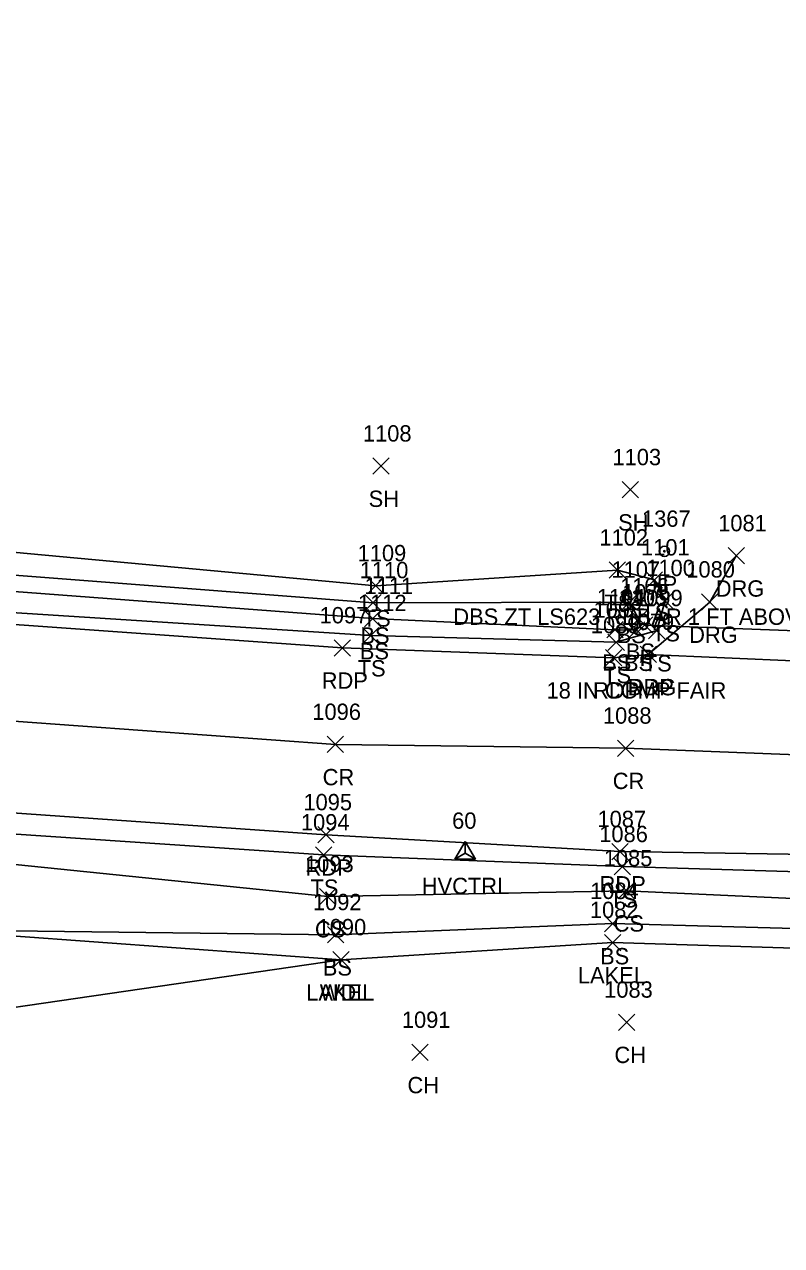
# Model space of a CAD drawing. Extents: x 1401404 to 1403982, y 557481 to 559873.
# Drawn here: x 1403448.2 to 1403540.8, y 558523.7 to 558673.1 of the extents above; entities that cross this region are included whole.
import ezdxf

# ---------------------------------------------------------------- set-up
doc = ezdxf.new("R2010")
doc.units = 0
for name, color, linetype in [('C_A', 7, 'Continuous'), ('C_I', 7, 'Continuous'), ('CPSM', 7, 'Continuous'), ('D_A', 7, 'Continuous'), ('D_C', 7, 'Continuous'), ('D_I', 7, 'Continuous'), ('D_TIC', 7, 'Continuous'), ('DCP', 7, 'Continuous'), ('L_A', 7, 'Continuous'), ('L_I', 7, 'Continuous'), ('L_TIC', 7, 'Continuous'), ('LAWA', 7, 'Continuous'), ('LAWE', 7, 'Continuous'), ('LELB', 7, 'Continuous'), ('M_A', 7, 'Continuous'), ('M_C', 7, 'Continuous'), ('M_I', 7, 'Continuous'), ('MPIR', 7, 'Continuous'), ('P_A', 7, 'Continuous'), ('P_I', 7, 'Continuous'), ('P_TIC', 7, 'Continuous'), ('PET', 7, 'Continuous'), ('PRC', 7, 'Continuous'), ('R_A', 7, 'Continuous'), ('R_I', 7, 'Continuous'), ('R_TIC', 7, 'Continuous'), ('RDG', 7, 'Continuous')]:
    doc.layers.add(name, color=color, linetype=linetype)

msp = doc.modelspace()

# ---------------------------------------------------------------- linework, layer by layer
at = {"layer": 'CPSM'}
for p, q in [((1403500.85, 558570.97), (1403502.1, 558573.13)), ((1403500.85, 558570.97), (1403502.1, 558571.69)), ((1403503.35, 558570.97), (1403502.1, 558573.13)), ((1403502.1, 558571.69), (1403502.1, 558573.13)), ((1403502.1, 558571.69), (1403502.1, 558571.69)), ((1403502.1, 558571.69), (1403503.35, 558570.97)), ((1403500.85, 558570.97), (1403503.35, 558570.97))]:
    msp.add_line(p, q, dxfattribs=at)
at = {"layer": 'D_TIC'}
for points in [[(1403523.07, 558598.63), (1403525.07, 558600.63)], [(1403525.07, 558598.63), (1403523.07, 558600.63)]]:
    msp.add_lwpolyline(points, dxfattribs=at)
at = {"layer": 'DCP'}
msp.add_lwpolyline([(1403554.56, 558598.47), (1403524.07, 558599.63)], dxfattribs=at)
at = {"layer": 'L_TIC'}
for points in [[(1403490.8, 558618.08), (1403492.8, 558620.08)], [(1403492.8, 558618.08), (1403490.8, 558620.08)], [(1403521.32, 558615.19), (1403523.32, 558617.19)], [(1403523.32, 558615.19), (1403521.32, 558617.19)], [(1403519.73, 558605.35), (1403521.73, 558607.35)], [(1403521.73, 558605.35), (1403519.73, 558607.35)], [(1403524.25, 558604.14), (1403526.25, 558606.14)], [(1403526.25, 558604.14), (1403524.25, 558606.14)], [(1403490.15, 558603.43), (1403492.15, 558605.43)], [(1403492.15, 558603.43), (1403490.15, 558605.43)], [(1403489.84, 558601.35), (1403491.84, 558603.35)], [(1403491.84, 558601.35), (1403489.84, 558603.35)], [(1403521.19, 558601.41), (1403523.19, 558603.41)], [(1403523.19, 558601.41), (1403521.19, 558603.41)], [(1403525.55, 558601.62), (1403527.55, 558603.62)], [(1403527.55, 558601.62), (1403525.55, 558603.62)], [(1403489.77, 558599.42), (1403491.77, 558601.42)], [(1403491.77, 558599.42), (1403489.77, 558601.42)], [(1403522.32, 558599.37), (1403524.32, 558601.37)], [(1403524.32, 558599.37), (1403522.32, 558601.37)], [(1403489.54, 558597.33), (1403491.54, 558599.33)], [(1403491.54, 558597.33), (1403489.54, 558599.33)], [(1403519.41, 558598.04), (1403521.41, 558600.04)], [(1403521.41, 558598.04), (1403519.41, 558600.04)], [(1403519.41, 558598.04), (1403521.41, 558600.04)], [(1403521.41, 558598.04), (1403519.41, 558600.04)], [(1403522.08, 558598), (1403524.08, 558600)], [(1403524.08, 558598), (1403522.08, 558600)], [(1403524.54, 558597.94), (1403526.54, 558599.94)], [(1403526.54, 558597.94), (1403524.54, 558599.94)], [(1403519.57, 558596.51), (1403521.57, 558598.51)], [(1403521.57, 558596.51), (1403519.57, 558598.51)], [(1403519.57, 558596.51), (1403521.57, 558598.51)], [(1403521.57, 558596.51), (1403519.57, 558598.51)], [(1403483.77, 558570.48), (1403485.77, 558572.48)], [(1403485.77, 558570.48), (1403483.77, 558572.48)], [(1403520.33, 558569.05), (1403522.33, 558571.05)], [(1403522.33, 558569.05), (1403520.33, 558571.05)], [(1403484.28, 558565.39), (1403486.28, 558567.39)], [(1403486.28, 558565.39), (1403484.28, 558567.39)], [(1403520.82, 558566.1), (1403522.82, 558568.1)], [(1403522.82, 558566.1), (1403520.82, 558568.1)], [(1403485.24, 558560.72), (1403487.24, 558562.72)], [(1403487.24, 558560.72), (1403485.24, 558562.72)], [(1403519.15, 558562.09), (1403521.15, 558564.09)], [(1403521.15, 558562.09), (1403519.15, 558564.09)], [(1403519.13, 558559.76), (1403521.13, 558561.76)], [(1403521.13, 558559.76), (1403519.13, 558561.76)], [(1403485.9, 558557.65), (1403487.9, 558559.65)], [(1403487.9, 558557.65), (1403485.9, 558559.65)], [(1403485.9, 558557.65), (1403487.9, 558559.65)], [(1403487.9, 558557.65), (1403485.9, 558559.65)], [(1403520.87, 558550.01), (1403522.87, 558552.01)], [(1403522.87, 558550.01), (1403520.87, 558552.01)], [(1403495.56, 558546.31), (1403497.56, 558548.31)], [(1403497.56, 558546.31), (1403495.56, 558548.31)]]:
    msp.add_lwpolyline(points, dxfattribs=at)
at = {"layer": 'LAWA'}
msp.add_lwpolyline([(1403486.9, 558558.65), (1403436.49, 558562.32), (1403410.5, 558564.81), (1403382.81, 558572.6), (1403367.26, 558569.55), (1403356.36, 558570.14), (1403328.83, 558581.39)], dxfattribs=at)
at = {"layer": 'LAWE'}
msp.add_lwpolyline([(1403696.34, 558534.54), (1403680.72, 558542.26), (1403669.4, 558548.58), (1403629.67, 558556.01), (1403603.5, 558551.35), (1403567.18, 558559.29), (1403520.13, 558560.76), (1403486.9, 558558.65), (1403434.25, 558550.99), (1403410.67, 558547.97), (1403397.83, 558540.52), (1403383.21, 558537.84), (1403361.63, 558542.24), (1403347.73, 558548.91), (1403330.86, 558557.2), (1403312.09, 558569.67), (1403266.36, 558595.5), (1403259.7, 558589.6), (1403257.9, 558590.94)], dxfattribs=at)
at = {"layer": 'LELB'}
for points in [[(1403567.19, 558568.67), (1403521.33, 558570.05), (1403484.77, 558571.48), (1403436.83, 558574.71), (1403390.35, 558579.88), (1403360.17, 558585.19), (1403345.93, 558587.28), (1403333.51, 558592.26), (1403317.51, 558600.62), (1403299, 558608.83), (1403282.94, 558617.97), (1403248.09, 558638.93), (1403217.12, 558660.94), (1403185.33, 558684.7), (1403148.79, 558715.46), (1403112.06, 558744.49), (1403074.23, 558776.66), (1403055.65, 558783.75), (1403043.18, 558796.21), (1403041.06, 558801.07)], [(1403520.57, 558597.51), (1403525.54, 558598.94), (1403526.55, 558602.62), (1403525.25, 558605.14), (1403520.73, 558606.35), (1403491.15, 558604.43), (1403440.56, 558609.1), (1403397, 558616.8), (1403381.31, 558624.94), (1403369.64, 558641.43)], [(1403520.41, 558599.04), (1403523.08, 558599), (1403523.32, 558600.37), (1403522.19, 558602.41), (1403490.84, 558602.35), (1403440.62, 558606.22), (1403396.23, 558612.97), (1403377.88, 558622.06), (1403365.41, 558636.4)], [(1403520.41, 558599.04), (1403490.77, 558600.42), (1403440.39, 558604.24), (1403395.77, 558611.21), (1403376.82, 558620.39), (1403364.4, 558635.59)], [(1403520.57, 558597.51), (1403490.54, 558598.33), (1403440.18, 558601.56), (1403395.32, 558608.26), (1403375.55, 558619.22), (1403363.26, 558634.4)], [(1403630.82, 558558.09), (1403605.04, 558560.57), (1403567.01, 558565), (1403521.82, 558567.1), (1403485.28, 558566.39), (1403436.65, 558571.38), (1403404.16, 558574.1), (1403374.76, 558578.32), (1403361.78, 558581.54), (1403361.26, 558576.4), (1403370.54, 558575)], [(1403725.58, 558523.67), (1403722.74, 558539.45), (1403706.56, 558549.47), (1403693.69, 558551), (1403674.49, 558552.83), (1403667, 558555.83), (1403630.82, 558558.09), (1403603.44, 558554.21), (1403567.5, 558561.8), (1403520.15, 558563.09), (1403486.24, 558561.72), (1403436.49, 558562.32), (1403409.67, 558557.93), (1403401.43, 558554.22), (1403392.6, 558552.11), (1403381.98, 558552.19), (1403374.37, 558554.61), (1403368.01, 558558.84), (1403339.85, 558573.14), (1403322.98, 558578.01)]]:
    msp.add_lwpolyline(points, dxfattribs=at)
at = {"layer": 'MPIR'}
for radius in [0.625, 0.0833]:
    msp.add_circle((1403526.47, 558608.65), radius, dxfattribs=at)
at = {"layer": 'P_TIC'}
for points in [[(1403486.06, 558595.83), (1403488.06, 558597.83)], [(1403488.06, 558595.83), (1403486.06, 558597.83)], [(1403519.25, 558594.63), (1403521.25, 558596.63)], [(1403521.25, 558594.63), (1403519.25, 558596.63)], [(1403523.49, 558595.02), (1403525.49, 558597.02)], [(1403525.49, 558595.02), (1403523.49, 558597.02)], [(1403485.23, 558584.01), (1403487.23, 558586.01)], [(1403487.23, 558584.01), (1403485.23, 558586.01)], [(1403520.72, 558583.55), (1403522.72, 558585.55)], [(1403522.72, 558583.55), (1403520.72, 558585.55)], [(1403484.08, 558572.95), (1403486.08, 558574.95)], [(1403486.08, 558572.95), (1403484.08, 558574.95)], [(1403520.05, 558570.89), (1403522.05, 558572.89)], [(1403522.05, 558570.89), (1403520.05, 558572.89)]]:
    msp.add_lwpolyline(points, dxfattribs=at)
at = {"layer": 'PET'}
for points in [[(1403567.32, 558571.16), (1403521.05, 558571.89), (1403485.08, 558573.95), (1403437.34, 558577.29), (1403390.93, 558583.55), (1403361.61, 558591.03), (1403321.82, 558602.54), (1403283.74, 558620.33), (1403244.19, 558645.3), (1403219.22, 558663.61), (1403205.44, 558672.12), (1403186.06, 558688.41), (1403150.64, 558718.11), (1403114.18, 558748.06), (1403076.2, 558780.03), (1403043.94, 558806.7), (1402997.13, 558841.77), (1402954.25, 558870.69), (1402915.87, 558893.53), (1402876.18, 558915.42), (1402801.33, 558955.21), (1402766.49, 558972.95)], [(1403552.49, 558594.8), (1403524.49, 558596.02), (1403520.25, 558595.63), (1403487.06, 558596.83), (1403440.08, 558600.18), (1403395.05, 558605.77), (1403363.07, 558611.97), (1403293.66, 558643.04), (1403283.54, 558648.26), (1403256.86, 558665.1), (1403232.94, 558682.45), (1403201.28, 558707.26), (1403164.55, 558736.67), (1403129.25, 558765.78)]]:
    msp.add_lwpolyline(points, dxfattribs=at)
at = {"layer": 'PRC'}
msp.add_lwpolyline([(1403567.87, 558582.77), (1403521.72, 558584.55), (1403486.23, 558585.01), (1403438.97, 558588.43), (1403393.1, 558594.9), (1403360.83, 558602.71), (1403288.92, 558631.6), (1403250.3, 558655.21), (1403225.89, 558672.35), (1403193.37, 558698.04), (1403157.15, 558726.96), (1403121.95, 558757.26), (1403083.22, 558789.98), (1403051.1, 558815.94), (1403004.27, 558851.49), (1402960.21, 558880.82), (1402921.63, 558903.82), (1402881.32, 558926.06), (1402807.32, 558964.73), (1402770.83, 558983.44)], dxfattribs=at)
at = {"layer": 'R_TIC'}
for points in [[(1403534.26, 558607.1), (1403536.26, 558609.1)], [(1403536.26, 558607.1), (1403534.26, 558609.1)], [(1403531.01, 558601.44), (1403533.01, 558603.44)], [(1403533.01, 558601.44), (1403531.01, 558603.44)], [(1403523.49, 558595.02), (1403525.49, 558597.02)], [(1403525.49, 558595.02), (1403523.49, 558597.02)]]:
    msp.add_lwpolyline(points, dxfattribs=at)
at = {"layer": 'RDG'}
msp.add_lwpolyline([(1403524.49, 558596.02), (1403532.01, 558602.44), (1403535.26, 558608.1)], dxfattribs=at)

# ---------------------------------------------------------------- texts
at = {"layer": 'C_A'}
msp.add_text('HVCTRL', height=2, dxfattribs=at).set_placement((1403496.79, 558566.69))
at = {"layer": 'C_I'}
msp.add_text('60', height=2, dxfattribs=at).set_placement((1403500.5, 558574.69))
at = {"layer": 'D_A'}
msp.add_text('P', height=2, dxfattribs=at).set_placement((1403523.45, 558594.63))
at = {"layer": 'D_C'}
msp.add_text('18 IN CGMP FAIR', height=2, dxfattribs=at).set_placement((1403512.05, 558590.63))
at = {"layer": 'D_I'}
msp.add_text('1075', height=2, dxfattribs=at).set_placement((1403521.3, 558602.63))
at = {"layer": 'L_A'}
for s, p in [('SH', (1403490.29, 558614.08)), ('SH', (1403520.81, 558611.19)), ('TS', (1403519.14, 558601.35)), ('TS', (1403523.66, 558600.14)), ('TS', (1403489.56, 558599.43)), ('BS', (1403489.28, 558597.35)), ('BS', (1403520.63, 558597.41)), ('TS', (1403524.95, 558597.62)), ('BS', (1403489.21, 558595.42)), ('BS', (1403521.76, 558595.37)), ('BS', (1403518.85, 558594.04)), ('BS', (1403518.85, 558594.04)), ('BS', (1403521.52, 558594)), ('TS', (1403523.95, 558593.94)), ('TS', (1403488.95, 558593.33)), ('TS', (1403518.98, 558592.51)), ('TS', (1403518.98, 558592.51)), ('TS', (1403483.18, 558566.48)), ('TS', (1403519.74, 558565.05)), ('CS', (1403483.72, 558561.39)), ('CS', (1403520.26, 558562.1)), ('BS', (1403518.6, 558558.09)), ('BS', (1403484.68, 558556.72)), ('LAKEL', (1403515.89, 558555.76)), ('LAKEL', (1403482.66, 558553.65)), ('WDL', (1403484.31, 558553.65)), ('CH', (1403520.36, 558546.01)), ('CH', (1403495.04, 558542.31))]:
    msp.add_text(s, height=2, dxfattribs=at).set_placement(p)
at = {"layer": 'L_I'}
for s, p in [('1108', (1403489.59, 558622.08)), ('1103', (1403520.12, 558619.19)), ('1102', (1403518.52, 558609.35)), ('1109', (1403488.94, 558607.43)), ('1101', (1403523.61, 558608.14)), ('1100', (1403524.25, 558605.62)), ('1110', (1403489.2, 558605.35)), ('1107', (1403519.99, 558605.41)), ('1111', (1403489.78, 558603.42)), ('1106', (1403521.06, 558603.37)), ('1112', (1403488.98, 558601.33)), ('1104', (1403518.2, 558602.04)), ('1104', (1403518.2, 558602.04)), ('1105', (1403520.87, 558602)), ('1099', (1403522.76, 558601.94)), ('1098', (1403517.8, 558600.51)), ('1098', (1403517.8, 558600.51)), ('1094', (1403482, 558574.48)), ('1086', (1403518.5, 558573.05)), ('1085', (1403519.05, 558570.1)), ('1093', (1403482.51, 558569.39)), ('1084', (1403517.38, 558566.09)), ('1092', (1403483.47, 558564.72)), ('1082', (1403517.36, 558563.76)), ('1090', (1403484.04, 558561.65)), ('1090', (1403484.04, 558561.65)), ('1083', (1403519.1, 558554.01)), ('1091', (1403494.35, 558550.31))]:
    msp.add_text(s, height=2, dxfattribs=at).set_placement(p)
at = {"layer": 'M_A'}
msp.add_text('IP', height=2, dxfattribs=at).set_placement((1403525.51, 558603.65))
at = {"layer": 'M_C'}
msp.add_text('DBS ZT LS623 REBAR 1 FT ABOVE', height=2, dxfattribs=at).set_placement((1403500.65, 558599.65))
at = {"layer": 'M_I'}
msp.add_text('1367', height=2, dxfattribs=at).set_placement((1403523.73, 558611.65))
at = {"layer": 'P_A'}
for s, p in [('RDP', (1403484.55, 558591.83)), ('RDP', (1403517.74, 558590.63)), ('RDP', (1403521.98, 558591.02)), ('CR', (1403484.66, 558580.01)), ('CR', (1403520.15, 558579.55)), ('RDP', (1403482.57, 558568.95)), ('RDP', (1403518.54, 558566.89))]:
    msp.add_text(s, height=2, dxfattribs=at).set_placement(p)
at = {"layer": 'P_I'}
for s, p in [('1097', (1403484.29, 558599.83)), ('1089', (1403517.47, 558598.63)), ('1079', (1403521.71, 558599.02)), ('1096', (1403483.4, 558588.01)), ('1088', (1403518.95, 558587.55)), ('1095', (1403482.31, 558576.95)), ('1087', (1403518.28, 558574.89))]:
    msp.add_text(s, height=2, dxfattribs=at).set_placement(p)
at = {"layer": 'R_A'}
for p in [(1403532.75, 558603.1), (1403529.5, 558597.44), (1403521.98, 558591.02)]:
    msp.add_text('DRG', height=2, dxfattribs=at).set_placement(p)
at = {"layer": 'R_I'}
for s, p in [('1081', (1403533.05, 558611.1)), ('1080', (1403529.15, 558605.44)), ('1079', (1403521.71, 558599.02))]:
    msp.add_text(s, height=2, dxfattribs=at).set_placement(p)

doc.saveas('drawing.dxf')
